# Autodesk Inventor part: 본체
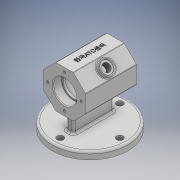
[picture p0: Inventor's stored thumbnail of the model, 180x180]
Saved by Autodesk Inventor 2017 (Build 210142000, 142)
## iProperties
Part Number: 본체
Material: 일반
Document SubType Name: Modeling
Designer: mrc
Density: 1 g/cm^3
Appearance: 기본값
Author: mrc
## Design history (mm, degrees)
sketch "스케치1" dims "d0" = 58
  geometry: L1 (12.012, 29)-(29, 12.012); L2 (29, 12.012)-(29, -12.012); L3 (29, -12.012)-(12.012, -29); L4 (12.012, -29)-(-12.012, -29); L5 (-12.012, -29)-(-29, -12.012); L6 (-29, -12.012)-(-29, 12.012); L7 (-29, 12.012)-(-12.012, 29); L8 (-12.012, 29)-(12.012, 29); 4 further points
  constraints: 16 end point, 2 coincident, 1 midpoint, 1 vertical alignment, 19 other
extrude "돌출1" new body sketch "스케치1" stored distance "d1" = 70; taper "d2" = 0 deg
node "작업 평면1"
sketch "스케치3"
  geometry: C1 r 52 at (0, 0); 1 further point
  constraints: 1 centre point, 1 coincident
  dimensions: "d4" = 104 diameter of C1
extrude "돌출2" join sketch "스케치3" distance "d5" = 10; taper "d6" = 0 deg
sketch "스케치4"
  geometry: L1 (-28, 0)-(28, 0); L2 (28, 0)-(28, -52); L3 (28, -52)-(-28, -52); L4 (-28, -52)-(-28, 0); L5 (52, -52)-(-52, -52) reference; 3 further points
  constraints: 8 end point, 4 midpoint, 2 parallel, 1 coincident, 1 horizontal, 1 perpendicular
  dimensions: "d7" = 56 distance of L2.end L3.end
extrude "돌출3" join sketch "스케치4" stored distance "d10" = 10; taper "d11" = 0 deg
sketch "스케치5"
  geometry: C1 r 14 at (0, 0); 1 further point
  constraints: 1 centre point, 1 coincident
  dimensions: "d12" = 28 diameter of C1
extrude "돌출4" cut sketch "스케치5" distance "d13" = 95.25; taper "d14" = 0 deg
sketch "스케치7"
  geometry: C1 r 16 at (0, 0); 1 further point
  constraints: 1 centre point, 1 coincident
  dimensions: "d15" = 32 diameter of C1
extrude "돌출5" cut sketch "스케치7" distance "d16" = 12; taper "d17" = 0 deg
sketch "스케치8"
  geometry: C1 r 22 at (0, 0); 1 further point
  constraints: 1 centre point, 1 coincident
  dimensions: "d18" = 44 diameter of C1
extrude "돌출6" cut sketch "스케치8" stored distance "d19" = 40; taper "d20" = 0 deg
sketch "스케치9"
  geometry: 2 further points
  constraints: 1 vertical alignment
  dimensions: "d21" = 23 distance of point (0, 0) point (0, 23)
hole "구멍1" sketch "스케치9" at (0, 23) diameter "d22" = 3.459; stored, may be unused: countersink angle "d26" = 90 deg, drill point angle "d28" = 118 deg; dims "d23" = 8, "d24" = 4, "d25" = 2, "d27" = 10
sketch "스케치10"
  geometry: C1 r 4.5 at (0, 41); 1 further point
  constraints: 1 centre point, 1 vertical alignment
  dimensions: "d32" = 9 diameter of C1; "d33" = 41 distance of point (0, 0) C1.centre
extrude "돌출7" cut sketch "스케치10" distance "d34" = 47; taper "d35" = 0 deg
sketch "스케치11"
  geometry: C1 r 10 at (-12.012, 35); 1 further point
  constraints: 1 centre point, 1 coincident
  dimensions: "d39" = 20 diameter of C1
extrude "돌출8" join sketch "스케치11" distance "d40" = 5; taper "d41" = 0 deg
sketch "스케치12"
  geometry: C1 r 8 at (0, 0); 1 further point
  constraints: 1 centre point, 1 coincident
  dimensions: "d42" = 16 diameter of C1
extrude "돌출9" cut sketch "스케치12" distance "d43" = 2; taper "d44" = 0 deg
hole "구멍2" diameter "d47" = 10.917; stored, may be unused: countersink angle "d51" = 90 deg, drill point angle "d53" = 118 deg; dims "d45" = 10, "d46" = 10, "d48" = 24, "d49" = 4, "d50" = 2, "d52" = 29.1
sketch "스케치14"
  geometry: L1 (6.005, -56.054)-(6.005, -14.575); L2 (6.005, -14.575)-(18.02, -14.575); L3 (18.02, -14.575)-(18.02, -56.054); L4 (18.02, -56.054)-(6.005, -56.054); L5 (12.012, -14.575)-(12.012, -56.054); L6 (12.012, -35)-(6.005, -35); L7 (-16.988, 0)-(-16.988, -70) reference
  constraints: 4 end point, 2 midpoint, 1 perpendicular, 1 point on line, 2 other
  dimensions: "d58" = 29 distance between parallel lines of L7 L5
extrude "돌출10" join sketch "스케치14" distance "d59" = 0.5; taper "d60" = 0 deg
fillet "모깎기1" dims "d61" = 3
chamfer "모따기1" distance "d62" = 1; stored, may be unused: second distance "d63" = 2, angle "d64" = 45 deg
fillet "모깎기2" dims "d65" = 1
fillet "모깎기3" dims "d66" = 1
fillet "모깎기5" dims "d68" = 0.3
sketch "스케치15"
  geometry: 1 further point
fillet "모깎기6" dims "d69" = 3
fillet "모깎기7" dims "d70" = 3
node "솔리드1"
mirror "미러1"
pattern_circular "원형 패턴1" dims angle "d30" = 360 deg
mirror "미러2"
pattern_circular "원형 패턴2" dims angle "d37" = 360 deg
other parameters: "d3" = -62
